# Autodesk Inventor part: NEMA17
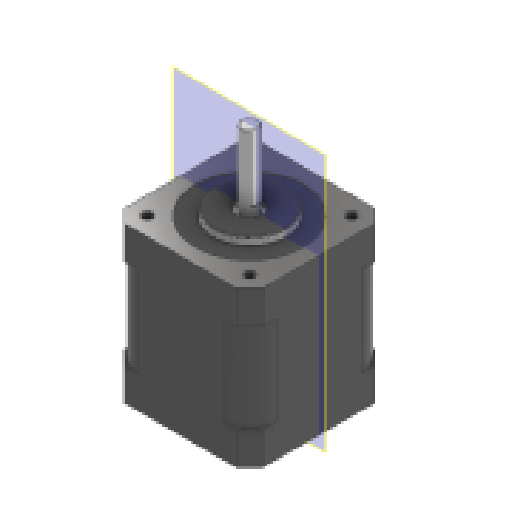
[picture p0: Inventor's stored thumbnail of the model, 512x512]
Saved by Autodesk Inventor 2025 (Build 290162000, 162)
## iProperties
Created: 2023-09
Part Number: NEMA17
Material: Genérico
Document SubType Name: Modeling
Designer: USUARIO
Density: 1 g/cm^3
Appearance: Valor por defecto
Author: USUARIO
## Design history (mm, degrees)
node "Annotazioni"
  node "Quota lineare 1" dims "d17" = 31, "d141" = 42 (derived)
  node "Quota lineare 2" dims "d17" = 31, "d144" = 42 (derived)
  node "Quota lineare 3" dims "d17" = 31, "d146" = 47.15 (derived)
  node "Quota lineare 4" dims "d17" = 31, "d149" = 22 (derived)
  node "Quota lineare 5" dims "d17" = 31, "d150" = 31 (derived)
sketch "Boceto1"
  geometry: L1 (0, 0)-(42, 0); L2 (42, 0)-(42, -42); L3 (42, -42)-(0, -42); L4 (0, -42)-(0, 0)
  constraints: 8 end point, 2 parallel, 1 horizontal, 1 perpendicular
  dimensions: "d105" = 42 distance of L2.end L3.end; "d106" = 42 distance of L1.end L2.end
extrude "Extrusión1" new body sketch "Boceto1" distance "d10" = 47.15; taper "d11" = 0 deg
sketch "Boceto2"
  geometry: L1 (-4, 42)-(-38, 42) reference; L2 (-38, 42)-(-42, 38) reference; L3 (-42, 38)-(-42, 4) reference; L4 (-42, 4)-(-38, 0) reference; L5 (-38, 0)-(-4, 0) reference; L6 (-4, 0)-(0, 4) reference; L7 (0, 4)-(0, 38) reference; L8 (0, 38)-(-4, 42) reference; L9 (-42, 38)-(-42, 4) reference; L10 (-42, 21)-(0, 21); L11 (-38, 0)-(-4, 0) reference; L12 (-21, 0)-(-21, 42); C1 r 11 at (-21, 21); C2 r 1.25 at (-36.5, 5.5); C3 r 1.25 at (-36.5, 36.5); C4 r 1.25 at (-5.5, 36.5); C5 r 1.25 at (-5.5, 5.5); C6 r 2.5 at (-21, 21); C7 r 16.5 at (-21, 21); 1 further point
  constraints: 7 centre point, 5 midpoint, 4 end point, 4 symmetric about line, 2 coincident
  dimensions: "d12" = 22 diameter of C1; "d13" = 2.5 diameter of C2; "d14" = 2.5 diameter of C3; "d15" = 2.5 diameter of C4; "d16" = 2.5 diameter of C5; "d17" = 31 distance of C3.centre C2.centre; "d18" = 31 distance of C4.centre C3.centre; "d19" = 5 diameter of C6; "d63" = 33 diameter of C7
  node "Contorno proyectado1"
extrude "Extrusión2" join sketch "Boceto2" distance "d20" = 2; taper "d21" = 0 deg
extrude "Extrusión3" join sketch "Boceto2" distance "d22" = 24; taper "d23" = 0 deg
hole "Agujero1" sketch "Boceto2" diameter "d24" = 2.5; stored, may be unused: countersink angle "d28" = 90 deg, drill point angle "d30" = 118 deg; dims "d25" = 6, "d26" = 3, "d27" = 2, "d29" = 4.5
extrude "Extrusión10" cut sketch "Boceto2" distance "d64" = 0.2; taper "d65" = 0 deg
fillet "Empalme1" dims "d66" = 0.2
sketch "Boceto11"
  geometry: C1 r 2.5 at (0, 0) reference; C2 r 3.75 at (0, 0); 1 further point
  constraints: 1 centre point, 1 coincident
  dimensions: "d67" = 7.5 diameter of C2
extrude "Extrusión11" cut sketch "Boceto11" distance "d68" = 1; taper "d69" = 0 deg
fillet "Empalme2" dims "d70" = 0.2
fillet "Empalme3" dims "d71" = 0.2
sketch "Boceto12"
  geometry: L1 (-4, -42)-(-38, -42) reference; L2 (0, -38)-(-4, -42) reference; L3 (0, -4)-(0, -38) reference; L4 (-4, 0)-(0, -4) reference; L5 (-38, 0)-(-4, 0) reference; L6 (-42, -4)-(-38, 0) reference; L7 (-42, -38)-(-42, -4) reference; L8 (-38, -42)-(-42, -38) reference; C1 r 3.75 at (-21, -21) reference; C2 r 1.25 at (-36.5, -5.5) reference; C3 r 1.25 at (-36.5, -5.5); C4 r 1.25 at (-5.5, -5.5); C5 r 1.25 at (-36.5, -36.5); C6 r 1.25 at (-5.5, -36.5); 1 further point
  constraints: 4 centre point, 1 coincident, 1 horizontal, 1 vertical, 6 other
  dimensions: "d74" = 31 distance of C3.centre C4.centre; "d77" = 31 distance of C3.centre C5.centre
  node "Contorno proyectado7"
  node "Schizzo - Serie rettangolare2" dims "d74" = 31, "d77" = 31
extrude "Extrusión12" cut sketch "Boceto12" distance "d80" = 1.5; taper "d81" = 0 deg
hole "Agujero2" sketch "Boceto12" diameter "d82" = 2.5; stored, may be unused: countersink angle "d86" = 90 deg, drill point angle "d88" = 118 deg; dims "d83" = 6, "d84" = 3, "d85" = 2, "d87" = 4.5
feature "Rosca1" dims "d89" = 4.25, "d90" = 0
feature "Rosca2" dims "d91" = 4.25, "d92" = 0
feature "Rosca3" dims "d93" = 4.25, "d94" = 0
feature "Rosca4" dims "d95" = 4.25, "d96" = 0
feature "Rosca5" dims "d97" = 4.25, "d98" = 0
feature "Rosca6" dims "d99" = 4.25, "d100" = 0
feature "Rosca7" dims "d101" = 4.25, "d102" = 0
feature "Rosca8" dims "d103" = 4.25, "d104" = 0
sketch "Schizzo13"
  geometry: L1 (2, 1.5)-(2, -1.5); A1 r 2.5 centre (0, 0) between (2, 1.5) and (2, -1.5) reference; A2 r 2.5 centre (0, 0) between (2, 1.5) and (2, -1.5) reference; 1 further point
  constraints: 2 end point, 2 point on circle, 1 vertical
  dimensions: "d107" = 2 distance from line of A1.centre L1
extrude "Estrusione13" cut sketch "Schizzo13" distance "d108" = 20; taper "d109" = 0 deg
sketch "Schizzo14"
  geometry: L1 (0, 0)-(0, 47.15) reference; L2 (42, 0)-(42, 47.15) reference; L3 (0, 37.15)-(42, 37.15); L4 (42, 37.15)-(42, 10); L5 (42, 10)-(0, 10); L6 (0, 10)-(0, 37.15); L7 (0, 47.15)-(42, 47.15) reference; L8 (0, 0)-(42, 0) reference; L9 (0, 0)-(42, 0) reference; L10 (42, 0)-(42, 47.15) reference; L11 (0, 47.15)-(42, 47.15) reference; L12 (0, 0)-(0, 47.15) reference; 2 further points
  constraints: 8 end point, 2 parallel, 2 point on line, 1 horizontal, 1 perpendicular
  dimensions: "d110" = 10 distance between parallel lines of L7 L3; "d111" = 10 distance between parallel lines of L8 L5
extrude "Estrusione14" cut sketch "Schizzo14" extent not by distance; stored distance "d112" = 0; taper "d113" = 0 deg
sketch "Schizzo15"
  geometry: L1 (42, 42)-(0, 42) reference; L2 (8, 42)-(34, 42); L3 (42, 34)-(42, 8); L4 (34, 0)-(8, 0); L5 (0, 8)-(0, 34); A1 r 8 centre (8, 34) between (8, 42) and (0, 34); A2 r 8 centre (8, 8) between (0, 8) and (8, 0); A3 r 8 centre (34, 8) between (34, 0) and (42, 8); A4 r 8 centre (34, 34) between (42, 34) and (34, 42); 3 further points
  constraints: 8 end point, 8 point on circle, 8 tangent, 4 centre point, 4 point on line, 3 equal radius, 2 parallel, 1 horizontal, 1 perpendicular
  dimensions: "d114" = 8 radius of A1
extrude "Estrusione15" join sketch "Schizzo15" stored distance "d115" = 10; taper "d116" = 0 deg
sketch "Schizzo16"
  geometry: L1 (-42, 42)-(-42, 0) reference; L2 (-4, 0)-(-38, 0); L3 (-42, 4)-(-42, 38); L4 (-38, 42)-(-4, 42); L5 (0, 38)-(0, 4); L6 (-4, 0)-(0, 4); L7 (0, 38)-(-4, 42); L8 (-38, 42)-(-42, 38); L9 (-42, 4)-(-38, 0); L10 (0, 42)-(-42, 42) reference; L11 (-42, 42)-(-42, 0) reference; L12 (-42, 0)-(0, 0) reference; L13 (0, 0)-(0, 42) reference; C1 r 16.5 at (-21, 21) reference; C2 r 1.5 at (-5.5, 36.5) reference; C3 r 1.5 at (-36.5, 5.5) reference; C4 r 1.5 at (-36.5, 36.5) reference; C5 r 1.5 at (-5.5, 5.5) reference; 13 further points
  constraints: 16 end point, 8 point on line, 2 parallel, 1 horizontal, 1 perpendicular
  dimensions: "d117" = 4 distance of L2.start point (0, 0); "d118" = 4 distance of L5.end point (0, 0) (= d117); "d119" = 4 distance of L5.start point (0, 42) (= d117); "d120" = 4 distance of L4.end point (0, 42) (= d119); "d121" = 4 distance of L4.start L1.start (= d117); "d122" = 4 distance of L3.end L1.start (= d121); "d123" = 4 distance of L3.start point (-42, 0) (= d117); "d124" = 4 distance of L2.end point (-42, 0) (= d123)
extrude "Estrusione16" cut sketch "Schizzo16" extent not by distance; stored distance "d125" = 0; taper "d126" = 0 deg
sketch "Schizzo18"
  geometry: L1 (9.568, -0.165)-(16.432, -0.165); L2 (16.432, -0.165)-(16.432, -6.785); L3 (16.432, -6.785)-(9.568, -6.785); L4 (9.568, -6.785)-(9.568, -0.165); L5 (16.75, -10)-(9.25, -10) reference; L6 (13, -10)-(13, -24.174); 1 further point
  constraints: 10 end point, 2 parallel, 1 horizontal, 1 midpoint, 1 perpendicular, 1 vertical, 1 other
extrude "Estrusione17" cut sketch "Schizzo18" distance "d127" = 1; taper "d128" = 0 deg
sketch "Schizzo19"
  geometry: L1 (26, 0)-(26, 27.15) reference; L2 (0, 0)-(0, 27.15) reference; L3 (24, 21.689)-(2, 21.689); L4 (0, 19.689)-(0, 10.651); L5 (2, 8.651)-(24, 8.651); L6 (26, 10.651)-(26, 19.689); A1 r 2 centre (2, 19.689) between (2, 21.689) and (0, 19.689); A2 r 2 centre (2, 10.651) between (0, 10.651) and (2, 8.651); A3 r 2 centre (24, 10.651) between (24, 8.651) and (26, 10.651); A4 r 2 centre (24, 19.689) between (26, 19.689) and (24, 21.689); 7 further points
  constraints: 8 end point, 8 point on circle, 8 tangent, 6 point on line, 4 centre point, 3 equal radius, 2 parallel, 1 horizontal, 1 perpendicular
  dimensions: "d129" = 2 radius of A1
extrude "Estrusione18" join sketch "Schizzo19" distance "d130" = 0.1; taper "d131" = 0 deg
sketch "Schizzo20"
  geometry: L1 (1.768, 19.705)-(23.84, 19.705); L2 (23.84, 19.705)-(23.84, 17.952); L3 (23.84, 17.952)-(1.768, 17.952); L4 (1.768, 17.952)-(1.768, 19.705); L5 (2.541, 14.6)-(25.13, 14.6); L6 (25.13, 14.6)-(25.13, 11.608); L7 (25.13, 11.608)-(2.541, 11.608); L8 (2.541, 11.608)-(2.541, 14.6)
  constraints: 4 other
sketch "Schizzo21"
  geometry: C1 r 0.625 at (11.812, -2.461); C2 r 0.625 at (13.519, -2.461); C3 r 0.625 at (11.812, -4.013); C4 r 0.625 at (13.344, -4.013); 1 further point
  constraints: 4 centre point
  dimensions: "d132" = 1.25 diameter of C1; "d133" = 1.25 diameter of C2; "d134" = 1.25 diameter of C3; "d135" = 1.25 diameter of C4
extrude "Estrusione19" join sketch "Schizzo21" distance "d136" = 5; taper "d137" = 0 deg
fillet "Raccordo4" dims "d138" = 1
node "Piano di lavoro4"
node "Sólido1"
node "Contorno proyectado6"
node "Linea chiusa proiettata8"
node "Linea chiusa proiettata9"
other parameters: "d31" = 19, "d139" = 7.70626 (derived), "d140" = 4.62744 (derived), "d142" = 1.65694 (derived), "d143" = 6.49634 (derived), "d145" = 8.63576 (derived), "d147" = 5.02646 (derived), "d148" = 4.17721 (derived)
